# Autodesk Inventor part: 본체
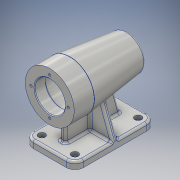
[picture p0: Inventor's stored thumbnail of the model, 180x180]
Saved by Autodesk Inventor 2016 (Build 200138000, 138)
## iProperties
Created: 2018-09
Part Number: 본체
Material: 알루미늄 6061
Document SubType Name: Modeling
Designer: 3sil_cad018
Density: 2.7 g/cm^3
Appearance: 알루미늄 - 평지
Mass: 733.476 g
Surface Area: 666.902 cm^2
Volume: 271.658 cm^3
Author: 3sil_cad018
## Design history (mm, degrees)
sketch "스케치1"
  geometry: L1 (0, 0)-(0, 34); L2 (0, 34)-(-28, 34); L3 (-28, 34)-(-112, 23.686); L4 (-112, 23.686)-(-112, 0); L5 (-112, 0)-(0, 0); A1 r 80 centre (-32, 0) between (-108.27, 24.144) and (-112, 0)
  constraints: 10 end point, 2 perpendicular, 2 point on circle, 2 point on line, 1 centre point, 1 parallel, 1 vertical
  dimensions: "d0" = 28 distance of L1.end L2.end; "d1" = 7 deg angle of L2 L3; "d2" = 112 distance between parallel lines of L1 L4; "d3" = 80 radius of A1; "d4" = 68 diameter of L2 L5
revolve "회전1" sketch "스케치1" stored, may be unused: angle "d5" = 90 deg
sketch "스케치2"
  geometry: L1 (0, 0)-(-15, 0); L2 (-15, 0)-(-15, 21); L3 (-15, 21)-(0, 21); L4 (0, 21)-(0, 0); L5 (-15, 0)-(-69, 0); L6 (-69, 0)-(-69, 24); L7 (-69, 24)-(-15, 24); L8 (-15, 24)-(-15, 0); L9 (-69, 0)-(-81, 0); L10 (-81, 0)-(-81, 21); L11 (-81, 21)-(-69, 21); L12 (-69, 21)-(-69, 0); L13 (-81, 0)-(-99, 0); L14 (-99, 0)-(-99, 17.5); L15 (-99, 17.5)-(-81, 17.5); L16 (-81, 17.5)-(-81, 0); L17 (-99, 0)-(-103, 0); L18 (-103, 0)-(-103, 16); L19 (-103, 16)-(-99, 16); L20 (-99, 16)-(-99, 0); L21 (-103, 0)-(-106, 0); L22 (-106, 0)-(-106, 10.5); L23 (-106, 10.5)-(-103, 10.5); L24 (-103, 10.5)-(-103, 0)
  constraints: 48 end point, 12 parallel, 6 horizontal, 6 perpendicular
  dimensions: "d6" = 15 distance of L2.end L3.end; "d7" = 54 distance of L6.end L7.end; "d8" = 12 distance of L10.end L11.end; "d9" = 18 distance of L14.end L15.end; "d10" = 4 distance of L18.end L19.end; "d11" = 3 distance of L22.end L23.end; "d12" = 42 diameter of L3 L1; "d13" = 48 diameter of L7 L5; "d14" = 42 diameter of L11 L5; "d15" = 35 diameter of L15 L9; "d16" = 32 diameter of L19 L17; "d17" = 21 diameter of L23 L21
revolve "회전2" sketch "스케치2" stored, may be unused: angle "d18" = 90 deg
sketch "스케치3" dims "d19" = 52
  geometry: 3 further points
  constraints: 1 coincident, 1 vertical alignment, 2 other
hole "구멍1" sketch "스케치3" at (0, 26) diameter "d20" = 3.242; stored, may be unused: countersink angle "d24" = 90 deg, drill point angle "d26" = 118 deg; dims "d21" = 8, "d22" = 4, "d23" = 2, "d25" = 11
node "작업 평면1"
sketch "스케치4"
  geometry: L1 (0, 35)-(112, 35); L2 (112, 35)-(112, -35); L3 (112, -35)-(0, -35); L4 (0, -35)-(0, 35); L5 (0, 35)-(112, -35); L6 (112, 35)-(0, -35); L7 (0, 34)-(0, -34) reference; 4 further points
  constraints: 12 end point, 4 midpoint, 2 parallel, 1 collinear, 1 horizontal, 1 horizontal alignment, 1 perpendicular
  dimensions: "d32" = 70 distance of L3.end L1.start; "d33" = 112 distance of L2.end L3.end
extrude "돌출1" join sketch "스케치4" distance "d34" = 10; taper "d35" = 0 deg
node "작업 평면2"
sketch "스케치7"
  geometry: L1 (0, -29.102)-(-8.297, -28.55); L2 (-8.297, -28.55)-(-19.33, -20.947); L3 (-19.33, -20.947)-(-35, -64); L4 (-35, -64)-(35, -64) reference; L5 (0, -64)-(0, -29.102); L6 (0, -64)-(-35, -64); L7 (0, -29.102)-(8.297, -28.55); L8 (8.297, -28.55)-(19.33, -20.947); L9 (19.33, -20.947)-(35, -64); L10 (35, -64)-(-35, -64); L11 (0, -64)-(35, -64); L12 (-35, -74)-(-35, -64) reference; 1 further point
  constraints: 20 end point, 5 symmetric about line, 2 point on line, 1 collinear, 1 midpoint, 1 perpendicular
  dimensions: "d41" = 20 deg angle of L3 L12
extrude "돌출2" join sketch "스케치7" stored distance "d42" = 8; taper "d43" = 0 deg
sketch "스케치8"
  geometry: L1 (-18, -33.939)-(-18, -64); L2 (-52, -64)-(0, -64) reference; L3 (0, -74)-(0, -64) reference; 1 further point
  constraints: 2 end point, 1 point on line, 1 vertical
  dimensions: "d44" = 18 distance between parallel lines of L1 L3
feature "리브1" sketch "스케치8" dims "d45" = 1, "d46" = 8, "d47" = 0, "d48" = 0, "d49" = 1, "d50" = 1
sketch "스케치9"
  geometry: L1 (-112, -64)-(-60, -64) reference; L2 (-94, -64)-(-84.115, -27.11); L3 (-108.27, -24.144)-(-60, -30.071) reference; L4 (-112, -74)-(-112, -64) reference; 1 further point
  constraints: 2 end point, 2 point on line
  dimensions: "d51" = 105 deg angle of L1 L2; "d52" = 18 distance from line of L2.start L4
feature "리브2" sketch "스케치9" dims "d53" = 1, "d54" = 8, "d55" = 0, "d56" = 0, "d57" = 1, "d58" = 1
fillet "모깎기1" dims "d59" = 12
sketch "스케치10"
  geometry: L1 (-18, -4)-(-52, -4) reference; L2 (-52, -4)-(-52, -35) reference; L3 (-52, -35)-(-60, -35) reference; L4 (-60, -35)-(-60, -4) reference; L5 (-60, -4)-(-94, -4) reference; L6 (-94, -4)-(-94, 4) reference; L7 (-94, 4)-(-60, 4) reference; L8 (-60, 4)-(-60, 35) reference; L9 (-100, 35)-(-60, 35) reference; L10 (-112, -23)-(-112, 23) reference; L11 (-60, -35)-(-100, -35) reference; L12 (-18, 4)-(-18, -4) reference; L13 (-52, 4)-(-18, 4) reference; L14 (-52, 35)-(-52, 4) reference; L15 (-60, 35)-(-52, 35) reference; L16 (-12, -35)-(-52, -35) reference; L17 (0, 23)-(0, -23) reference; L18 (-52, 35)-(-12, 35) reference; A1 r 12 centre (-100, 23) between (-100, 35) and (-112, 23) reference; A2 r 12 centre (-100, -23) between (-112, -23) and (-100, -35) reference; A3 r 12 centre (-12, -23) between (-12, -35) and (0, -23) reference; A4 r 12 centre (-12, 23) between (0, 23) and (-12, 35) reference; 1 further point
hole "구멍2" sketch "스케치10" at (-100, -23), (-100, 23), (-12, -23), (-12, 23) diameter "d60" = 5.5; stored, may be unused: countersink angle "d64" = 90 deg, drill point angle "d66" = 118 deg; dims "d61" = 8, "d62" = 9.5, "d63" = 5.4, "d65" = 11
fillet "모깎기2" dims "d67" = 3
fillet "모깎기3" dims "d68" = 3
chamfer "모따기1" distance "d69" = 1; stored, may be unused: second distance "d70" = 2, angle "d71" = 45 deg
fillet "모깎기4" dims "d72" = 0.3
sketch "스케치11"
  geometry: L1 (88, 0)-(0, 0) reference; L2 (100, 0)-(100, 7) reference; 2 further points
  constraints: 1 other
  dimensions: "d73" = 3 distance from line of L1 point (44, 3); "d74" = 56 distance from line of L2 point (44, 3)
feature "엠보싱1" sketch "스케치11" dims "d75" = 0.5, "d76" = 0
fillet "모깎기5" dims "d77" = 3
fillet "모깎기6" dims "d78" = 3
fillet "모깎기7" dims "d79" = 3
node "솔리드1"
pattern_circular "원형 패턴1" dims angle "d28" = 360 deg
node "절단 모서리 투영2"
other parameters: "d30" = -74, "d40" = -56
